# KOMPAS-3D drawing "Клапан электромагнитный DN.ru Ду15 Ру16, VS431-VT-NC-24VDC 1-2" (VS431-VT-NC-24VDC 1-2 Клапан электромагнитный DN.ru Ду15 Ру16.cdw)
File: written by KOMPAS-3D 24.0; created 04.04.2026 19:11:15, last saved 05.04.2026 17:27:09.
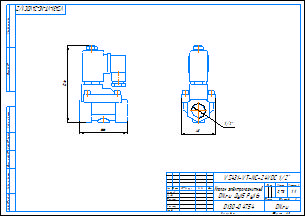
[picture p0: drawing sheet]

Document properties: c3d_UniqueCompID: ef56311e-7521-43dc-8291-0e6108b3d81d; Обозначение: VS400-ET-NC-220VAC 1-2; Наименование: Клапан электромагнитный DN.ru Ду15 Ру16; Автор: artio; Класс точности: c; Знак неуказанной шероховатости: Шероховатость не задана; Рассекать на разрезах: Да; c3d_UniqueCompID: ef56311e-7521-43dc-8291-0e6108b3d81d; Обозначение: VS400-ET-NC-220VAC 3-8; Наименование: Клапан электромагнитный DN.ru Ду10 Ру16; Автор: artio; Класс точности: c; Знак неуказанной шероховатости: Шероховатость не задана; Рассекать на разрезах: Да; Автор: artio; Форматы листов документа: A3; Полное имя файла: VS431-VT-NC-24VDC 1-2 Клапан электромагнитный DN.ru Ду15 Ру16.m3d; Масса: 0.732; Наименование: Клапан электромагнитный DN.ru Ду15 Ру16; Количество листов документа: 1; Примечание: D130-04754

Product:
- Body: Тело 1  | qty 1
    Масса: 1.030062
- Part/product: Клапан электромагнитный DN.ru Ду15 Ру16  | designation VS431-VT-NC-24VDC 1-2
    Масса: 0.732
    Раздел спецификации: Прочие изделия
    Примечание: D130-04754
    additional columns: ef56311e-7521-43dc-8291-0e6108b3d81d; VS400-ET-NC-220VAC 1-2; artio; c; Шероховатость не задана; Да

Views: Вид 1, Спереди, Проекционный вид 2
Referenced files in C:\Users\artio\OneDrive\Рабочий стол\Клапан электромагнитный DN.ru\VS400-ET-NC\VS400-ET-NC-24VDC\: VS400-ET-NC-24VDC 3-8 Клапан электромагнитный DN.ru Ду10 Ру16.m3d
Referenced files in C:\Users\artio\OneDrive\Рабочий стол\Клапан электромагнитный DN.ru\VS431\VS431-VT-NC\VS431-VT-NC-24VDC\Ду15\: VS431-VT-NC-24VDC 1-2 Клапан электромагнитный DN.ru Ду15 Ру16.m3d
Referenced files in C:\Users\artio\OneDrive\Рабочий стол\Клапан электромагнитный DN.ru\VS400-ET-NC\: VS400-ET-NC-24VDC 3-8 Клапан электромагнитный DN.ru Ду10 Ру16.cdw
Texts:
  VS431-VT-NC-24VDC 1-2
  Клапан электромагнитный
  DN.ru Ду15 Ру16
  VS431-VT-NC-24VDC 1/2"
  VS431-VT-NC-24VDC 1/2"-
  Клапан электромагнитный DN.ru Ду15 Ру16
  VS431-VT-NC-24VDC 1-2 Клапан электромагнитный DN.ru Ду15 Ру16
Dimensions and other numbers on the sheet: 0; 3; 2; 4; 48; 1/2"; 66; 106; 1:1; 1; 0,73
